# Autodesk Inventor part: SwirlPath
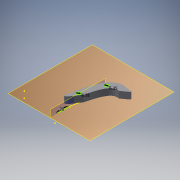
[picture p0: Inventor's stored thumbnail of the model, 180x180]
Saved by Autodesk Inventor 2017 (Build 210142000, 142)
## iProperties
Created: 2017-05
Part Number: SwirlPath
Material: Generic
Document SubType Name: Modeling
Designer: 1460374
Density: 1 g/cm^3
Appearance: Default
Author: 1460374
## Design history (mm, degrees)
workplane "Work Plane1"
sketch "Sketch1" dims "d0" = 3
  geometry: L1 (83.27, 89.195)-(82.782, 86.235); L2 (56.337, 26.788)-(53.377, 27.276); A1 r 6.35 centre (85.079, 80.315) between (86.898, 86.399) and (86.898, 74.231) reference; 2 further points
  constraints: 4 end point, 1 perpendicular, 1 point on circle, 6 other
extrude "Extrusion1" new body sketch "Sketch1" distance "d1" = 12; taper "d2" = 0 deg
workplane "Work Plane2"
sketch "Sketch2"
  geometry: L1 (53.377, 27.276)-(53.12, 7.277); 1 further point
  constraints: 2 end point
  dimensions: "d3" = 20 distance of L1.start L1.end
workplane "Work Plane4"
  workplane "Work Plane3"
sketch "Sketch6"
  geometry: 1 further point
workplane "Work Plane5"
sketch "Sketch7"
  geometry: 3 further points
  constraints: 1 other
thicken "Thicken2" dims "d9" = 10, "d10" = 10
sketch "Sketch8"
  geometry: C1 r 3.175 at (66.441, 83.59); C2 r 3.175 at (53.053, 45.605); 1 further point
  constraints: 2 centre point
  dimensions: "d11" = 6.35 diameter of C1; "d12" = 6.35 diameter of C2
workplane "Work Plane6"
sketch "Sketch9"
  geometry: 1 further point
sketch "Sketch10"
  geometry: L1 (12, 0)-(0, 0) reference; L2 (12, 13)-(0, 13) reference; L3 (12, 0)-(0, 0); L4 (0, 0)-(0, 13); L5 (0, 13)-(12, 13); L6 (12, 13)-(12, 0); 1 further point
  constraints: 8 end point, 2 parallel, 1 horizontal, 1 perpendicular
extrude "Extrusion4" join sketch "Sketch10" distance "d15" = 14; taper "d16" = 0 deg
chamfer "Chamfer1" distance "d17" = 11; stored, may be unused: second distance "d18" = 2, angle "d19" = 45 deg
sketch "Sketch11"
  geometry: A1 r 6.35 centre (88.718, 80.315) between (86.898, 74.231) and (86.898, 86.399) reference; A2 r 6.35 centre (85.079, 80.315) between (86.898, 86.399) and (86.898, 74.231) reference; 1 further point
extrude "Extrusion5" cut sketch "Sketch11" distance "d20" = 14; taper "d21" = 0 deg
fillet "Fillet1" dims "d22" = 15
chamfer "Chamfer2" distance "d23" = 11; stored, may be unused: second distance "d24" = 2, angle "d25" = 45 deg
chamfer "Chamfer3" distance "d26" = 11; stored, may be unused: second distance "d27" = 2, angle "d28" = 45 deg
body "Solid1"
node "Reference1"
node "Reference2"
node "Reference3"
other parameters: "d4" = 90 deg
